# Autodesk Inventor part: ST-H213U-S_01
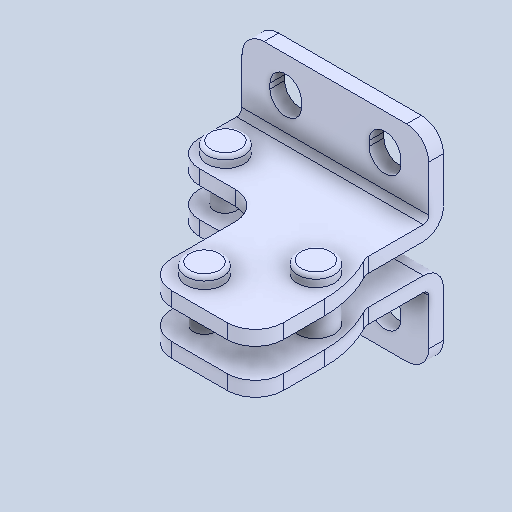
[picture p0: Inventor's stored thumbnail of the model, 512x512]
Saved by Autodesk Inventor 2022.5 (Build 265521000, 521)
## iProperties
Created: 2024-07
Part Number: ST-H213U-S_01
Material: 一般
Document SubType Name: Modeling
Designer: ImaoCorp
Density: 1 g/cm^3
Appearance: 既定
Author: ImaoCorp
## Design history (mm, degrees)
feature "ST-H213U-S_01"
node "ソリッド1"
